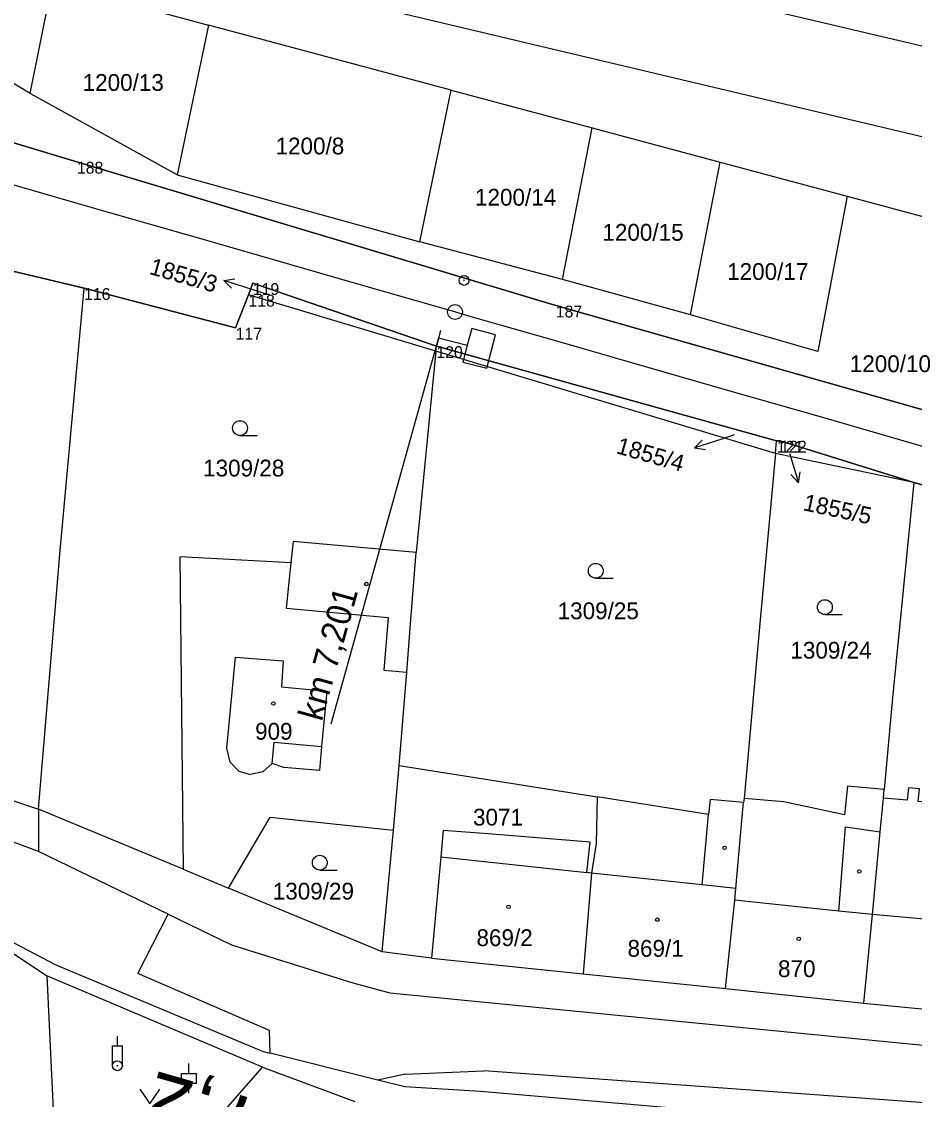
# Model space of a CAD drawing. Extents: x -779330 to -774454, y -1144748 to -1142831.
# Drawn here: x -777328.3 to -777238, y -1143849.7 to -1143740.6 of the extents above; entities that cross this region are included whole.
import ezdxf

# ---------------------------------------------------------------- set-up
doc = ezdxf.new("R2010")
doc.units = 0
for name, color, linetype in [('Hranice parcel', 7, 'Continuous'), ('Parcelní čísla', 7, 'Continuous'), ('Pop  PČ popisy', 7, 'Continuous'), ('Poz předměty', 7, 'Continuous'), ('SŽDC', 7, 'Continuous'), ('Vnitřní kresba', 7, 'Continuous'), ('Vrstva 1', 7, 'Continuous'), ('Vrstva 53', 7, 'Continuous'), ('Vrstva 60', 7, 'Continuous'), ('Vrstva 7', 7, 'Continuous'), ('Značky budov', 7, 'Continuous'), ('Značky kultur', 7, 'Continuous')]:
    doc.layers.add(name, color=color, linetype=linetype)

msp = doc.modelspace()

# ---------------------------------------------------------------- linework, layer by layer
at = {"layer": 'Hranice parcel'}
for p, q in [((-777327.45, -1143747.9), (-777325.2, -1143736.7)), ((-777327.45, -1143747.9), (-777342.31, -1143738.85)), ((-777309.4, -1143740.97), (-777312.56, -1143756.11)), ((-777284.85, -1143747.54), (-777309.4, -1143740.97)), ((-777288.01, -1143762.89), (-777284.85, -1143747.54)), ((-777284.85, -1143747.54), (-777270.58, -1143751.37)), ((-777312.56, -1143756.11), (-777327.45, -1143747.9)), ((-777273.56, -1143766.7), (-777270.58, -1143751.37)), ((-777270.58, -1143751.37), (-777257.62, -1143754.85)), ((-777260.64, -1143770.3), (-777257.62, -1143754.85)), ((-777257.62, -1143754.85), (-777244.78, -1143758.29)), ((-777312.56, -1143756.11), (-777288.01, -1143762.89)), ((-777244.78, -1143758.29), (-777232.23, -1143761.66)), ((-777273.56, -1143766.7), (-777288.01, -1143762.89)), ((-777260.64, -1143770.3), (-777273.56, -1143766.7)), ((-777286.39, -1143773.98), (-777305.36, -1143768.26)), ((-777286.39, -1143773.98), (-777286.34, -1143773.47)), ((-777251.91, -1143783.05), (-777286.34, -1143773.47)), ((-777286.39, -1143773.98), (-777288.38, -1143794.34)), ((-777252.03, -1143784.34), (-777286.39, -1143773.98)), ((-777252.03, -1143784.34), (-777251.91, -1143783.05)), ((-777238.03, -1143787.25), (-777252.03, -1143784.34)), ((-777223.03, -1143791.52), (-777238.03, -1143787.25)), ((-777290.68, -1143822.46), (-777290.09, -1143815.91)), ((-777290.09, -1143815.91), (-777270.07, -1143819.08)), ((-777241.11, -1143819.21), (-777241.04, -1143818.34)), ((-777255.21, -1143819.24), (-777255.25, -1143819.66)), ((-777251.18, -1143819.6), (-777255.21, -1143819.24)), ((-777311.97, -1143826.4), (-777326.6, -1143820.32)), ((-777326.6, -1143820.32), (-777326.59, -1143824.61)), ((-777326.59, -1143824.61), (-777334.23, -1143821.79)), ((-777291.81, -1143834.78), (-777290.68, -1143822.46)), ((-777281.11, -1143822.84), (-777285.64, -1143822.5)), ((-777313.47, -1143830.96), (-777326.59, -1143824.61)), ((-777311.97, -1143826.4), (-777307.37, -1143828.31)), ((-777270.65, -1143826.8), (-777271.48, -1143836.99)), ((-777291.81, -1143834.78), (-777307.37, -1143828.31)), ((-777336.84, -1143829.8), (-777325.74, -1143837.19)), ((-777316.56, -1143836.95), (-777313.47, -1143830.96)), ((-777286.82, -1143835.42), (-777291.81, -1143834.78)), ((-777286.82, -1143835.42), (-777271.48, -1143836.99)), ((-777303.21, -1143842.75), (-777316.56, -1143836.95)), ((-777271.48, -1143836.99), (-777257.08, -1143838.49)), ((-777303.94, -1143846.43), (-777325.74, -1143837.19)), ((-777325.74, -1143837.19), (-777324.77, -1143858.48)), ((-777257.08, -1143838.49), (-777243.1, -1143839.97)), ((-777243.1, -1143839.97), (-777230.13, -1143841.26)), ((-777303.16, -1143845.03), (-777303.21, -1143842.75)), ((-777303.94, -1143846.43), (-777294.6, -1143849.93))]:
    msp.add_line(p, q, dxfattribs=at)
for points in [[(-777325.2, -1143736.7), (-777318.15, -1143738.6), (-777309.4, -1143740.97)], [(-776969.85, -1143863.66), (-776987.47, -1143857.88), (-777014.89, -1143846.57), (-777042.6, -1143836.95), (-777069.03, -1143828.43), (-777082.24, -1143824.08), (-777130.76, -1143810.13), (-777274.26, -1143769.36), (-777322.71, -1143754.8), (-777354.97, -1143745.11)], [(-777244.78, -1143758.29), (-777247.73, -1143773.99), (-777260.64, -1143770.3)], [(-777321.99, -1143767.59), (-777335.02, -1143764.48), (-777339.43, -1143766.44), (-777340.59, -1143770.61), (-777348.72, -1143768.82), (-777354.56, -1143760.13)], [(-777354.56, -1143760.13), (-777350.41, -1143771.21), (-777345.05, -1143784.18), (-777331.15, -1143818.8), (-777326.6, -1143820.32)], [(-777286.34, -1143773.47), (-777304.91, -1143767.08), (-777305.36, -1143768.26)], [(-777326.6, -1143820.32), (-777324.39, -1143794.13), (-777321.99, -1143767.59)], [(-777305.36, -1143768.26), (-777306.65, -1143771.6), (-777321.99, -1143767.59)], [(-777238.03, -1143787.25), (-777251.55, -1143783.03), (-777251.91, -1143783.05)], [(-777252.03, -1143784.34), (-777253.62, -1143801.54), (-777255.21, -1143819.24)], [(-777238.03, -1143787.25), (-777240.18, -1143809.05), (-777241.04, -1143818.34)], [(-777288.38, -1143794.34), (-777300.82, -1143793.24), (-777301.05, -1143795.41), (-777312.29, -1143794.79), (-777311.97, -1143826.4)], [(-777290.09, -1143815.91), (-777289.33, -1143806.45), (-777288.91, -1143801.12), (-777288.38, -1143794.34)], [(-777241.04, -1143818.34), (-777244.73, -1143818), (-777245.06, -1143820.91), (-777251.18, -1143819.6)], [(-777227.11, -1143820.99), (-777234.21, -1143819.88), (-777237.58, -1143819.54), (-777237.46, -1143818.26), (-777238.58, -1143818.16), (-777238.7, -1143819.43), (-777241.11, -1143819.21)], [(-777270.07, -1143819.08), (-777270.18, -1143823.82), (-777270.65, -1143826.8)], [(-777255.25, -1143819.66), (-777258.65, -1143819.35), (-777258.79, -1143820.87), (-777270.07, -1143819.08)], [(-777256.03, -1143828.35), (-777255.35, -1143820.74), (-777255.25, -1143819.66)], [(-777243.1, -1143839.97), (-777242.2, -1143831), (-777241.43, -1143822.63), (-777241.11, -1143819.21)], [(-777307.37, -1143828.31), (-777303.15, -1143821.13), (-777290.68, -1143822.46)], [(-777285.64, -1143822.5), (-777285.88, -1143825.17), (-777286.82, -1143835.42)], [(-777270.65, -1143826.8), (-777271.1, -1143826.75), (-777270.77, -1143823.67), (-777281.11, -1143822.84)], [(-777257.08, -1143838.49), (-777256.14, -1143829.55), (-777256.03, -1143828.35)], [(-777336.84, -1143829.8), (-777324.83, -1143836.1), (-777303.85, -1143844.86), (-777303.16, -1143845.03)], [(-777313.47, -1143830.96), (-777307.07, -1143834.06), (-777294.79, -1143837.91), (-777291.06, -1143838.91), (-777215.44, -1143846.33), (-777156.34, -1143852.08), (-777155.61, -1143848.73), (-777137.5, -1143850.27)], [(-776998.39, -1143882.22), (-777014.02, -1143874.66), (-777035.36, -1143870.54), (-777167.58, -1143858.82), (-777281.88, -1143848.9), (-777289.53, -1143848.43), (-777292.27, -1143847.75), (-777303.16, -1143845.03)], [(-777322.91, -1143859.24), (-777317.16, -1143861.59), (-777303.94, -1143846.43)]]:
    msp.add_lwpolyline(points, dxfattribs=at)
at = {"layer": 'Pop  PČ popisy'}
for p, q in [((-777307.84, -1143766.8), (-777306.74, -1143766.64)), ((-777304.99, -1143767.73), (-777307.84, -1143766.8)), ((-777307.84, -1143766.8), (-777307.05, -1143767.59)), ((-777303.43, -1143768.24), (-777304.99, -1143767.73)), ((-777256.2, -1143782.45), (-777257.37, -1143782.84)), ((-777257.37, -1143782.84), (-777260.22, -1143783.77)), ((-777260.22, -1143783.77), (-777259.43, -1143782.98)), ((-777260.22, -1143783.77), (-777259.12, -1143783.93)), ((-777250.61, -1143784.33), (-777250.59, -1143784.41)), ((-777250.59, -1143784.41), (-777249.71, -1143787.28)), ((-777249.71, -1143787.28), (-777250.48, -1143786.47)), ((-777249.71, -1143787.28), (-777249.53, -1143786.18))]:
    msp.add_line(p, q, dxfattribs=at)
at = {"layer": 'Poz předměty'}
for p, q in [((-777318.61, -1143844.3), (-777318.61, -1143843.3)), ((-777319.11, -1143844.3), (-777318.11, -1143844.3)), ((-777319.11, -1143846.3), (-777319.11, -1143844.3)), ((-777318.11, -1143846.3), (-777318.11, -1143844.3))]:
    msp.add_line(p, q, dxfattribs=at)
for radius in [0.5, 0.0303]:
    msp.add_circle((-777318.61, -1143846.3), radius, dxfattribs=at)
at = {"layer": 'SŽDC'}
for points in [[(-777130.76, -1143810.13), (-777274.26, -1143769.36), (-777322.71, -1143754.8), (-777354.97, -1143745.11), (-777360.64, -1143743.54), (-777364.22, -1143742.54), (-777366.62, -1143741.88), (-777370.73, -1143741.3), (-777400.53, -1143733.41), (-777442.54, -1143720.48), (-777447.49, -1143719.07), (-777546.18, -1143690.99), (-777600.4, -1143675.56), (-777619.92, -1143670.03)], [(-777340.59, -1143770.61), (-777339.43, -1143766.44), (-777335.02, -1143764.48), (-777321.99, -1143767.59), (-777306.65, -1143771.6), (-777305.36, -1143768.26), (-777304.91, -1143767.08), (-777286.34, -1143773.47), (-777251.91, -1143783.05), (-777251.55, -1143783.03), (-777238.03, -1143787.25), (-777223.03, -1143791.52), (-777208.67, -1143795.71), (-777200.02, -1143798.42), (-777184.53, -1143802.76), (-777180.06, -1143803.98), (-777171.85, -1143806.53), (-777132.17, -1143818.13)]]:
    msp.add_lwpolyline(points, dxfattribs=at)
at = {"layer": 'Vnitřní kresba'}
for p, q in [((-777312.68, -1143725.18), (-777111.56, -1143772.88)), ((-777113.15, -1143781.74), (-777316.11, -1143733.54)), ((-777301.05, -1143795.41), (-777301.54, -1143800)), ((-777301.54, -1143800), (-777291.2, -1143800.92)), ((-777291.2, -1143800.92), (-777291.66, -1143806.27)), ((-777307.53, -1143814.17), (-777306.67, -1143804.95)), ((-777306.67, -1143804.95), (-777301.84, -1143805.3)), ((-777301.84, -1143805.3), (-777302.02, -1143807.96)), ((-777291.66, -1143806.27), (-777289.33, -1143806.45)), ((-777302.02, -1143807.96), (-777297.43, -1143808.38)), ((-777297.43, -1143808.38), (-777297.95, -1143813.99)), ((-777307.2, -1143815.56), (-777307.53, -1143814.17)), ((-777302.94, -1143815.72), (-777302.75, -1143813.55)), ((-777302.75, -1143813.55), (-777297.95, -1143813.99)), ((-777297.95, -1143813.99), (-777298.17, -1143816.4)), ((-777306.31, -1143816.47), (-777307.2, -1143815.56)), ((-777303.9, -1143816.56), (-777302.94, -1143815.72)), ((-777301.78, -1143816.1), (-777302.94, -1143815.72)), ((-777298.17, -1143816.4), (-777301.78, -1143816.1)), ((-777306.31, -1143816.47), (-777305.15, -1143816.82)), ((-777303.9, -1143816.56), (-777305.15, -1143816.82)), ((-777259.43, -1143827.99), (-777258.79, -1143820.87)), ((-777245.61, -1143830.64), (-777244.96, -1143822.12)), ((-777244.96, -1143822.12), (-777241.43, -1143822.63)), ((-777285.88, -1143825.17), (-777271.1, -1143826.75)), ((-777259.43, -1143827.99), (-777270.65, -1143826.8)), ((-777256.03, -1143828.35), (-777259.43, -1143827.99)), ((-777253.62, -1143829.81), (-777256.14, -1143829.55)), ((-777245.61, -1143830.64), (-777253.62, -1143829.81)), ((-777242.2, -1143831), (-777245.61, -1143830.64)), ((-777230.17, -1143832.07), (-777242.2, -1143831)), ((-777289.51, -1143847.16), (-777281.53, -1143846.8)), ((-777216.02, -1143851.57), (-777281.53, -1143846.8)), ((-777289.51, -1143847.16), (-777292.27, -1143847.75))]:
    msp.add_line(p, q, dxfattribs=at)
at = {"layer": 'Vrstva 1'}
msp.add_lwpolyline([(-777162.91, -1143804.93), (-777170.68, -1143802.7), (-777181.57, -1143799.57), (-777188.57, -1143797.56), (-777198.81, -1143794.61), (-777207.68, -1143792.07), (-777219.79, -1143788.59), (-777229.54, -1143785.79), (-777237.24, -1143783.57), (-777247.71, -1143780.56), (-777256.74, -1143777.97), (-777268.3, -1143774.64), (-777273.69, -1143773.09), (-777283.04, -1143770.41), (-777284.04, -1143770.12), (-777284.38, -1143770.02), (-777293.19, -1143767.49), (-777295.09, -1143766.94), (-777310.28, -1143762.58), (-777319.98, -1143759.79), (-777330, -1143756.91)], dxfattribs=at)
at = {"layer": 'Vrstva 53'}
for points in [[(-777619.92, -1143670.03), (-777600.4, -1143675.56), (-777546.18, -1143690.99), (-777447.49, -1143719.07), (-777442.54, -1143720.48), (-777400.53, -1143733.41), (-777370.73, -1143741.3), (-777366.62, -1143741.88), (-777364.22, -1143742.54), (-777360.64, -1143743.54), (-777354.97, -1143745.11), (-777322.71, -1143754.8), (-777274.26, -1143769.36), (-777130.76, -1143810.13)], [(-777619.92, -1143670.03), (-777600.4, -1143675.56), (-777546.18, -1143690.99), (-777447.49, -1143719.07), (-777442.54, -1143720.48), (-777400.53, -1143733.41), (-777370.73, -1143741.3), (-777366.62, -1143741.88), (-777364.22, -1143742.54), (-777360.64, -1143743.54), (-777354.97, -1143745.11), (-777322.71, -1143754.8), (-777274.26, -1143769.36), (-777130.76, -1143810.13)], [(-777132.17, -1143818.13), (-777171.85, -1143806.53), (-777180.06, -1143803.98), (-777184.53, -1143802.76), (-777200.02, -1143798.42), (-777208.67, -1143795.71), (-777223.03, -1143791.52), (-777238.03, -1143787.25), (-777251.55, -1143783.03), (-777251.91, -1143783.05), (-777286.34, -1143773.47), (-777304.91, -1143767.08), (-777305.36, -1143768.26), (-777306.65, -1143771.6), (-777321.99, -1143767.59), (-777335.02, -1143764.48), (-777339.43, -1143766.44), (-777340.59, -1143770.61)], [(-777132.17, -1143818.13), (-777171.85, -1143806.53), (-777180.06, -1143803.98), (-777184.53, -1143802.76), (-777200.02, -1143798.42), (-777208.67, -1143795.71), (-777223.03, -1143791.52), (-777238.03, -1143787.25), (-777251.55, -1143783.03), (-777251.91, -1143783.05), (-777286.34, -1143773.47), (-777304.91, -1143767.08), (-777305.36, -1143768.26), (-777306.65, -1143771.6), (-777321.99, -1143767.59), (-777335.02, -1143764.48), (-777339.43, -1143766.44), (-777340.59, -1143770.61)]]:
    msp.add_lwpolyline(points, dxfattribs=at)
at = {"layer": 'Vrstva 60'}
for p, q in [((-777322.71, -1143754.8), (-777322.71, -1143754.8)), ((-777304.91, -1143767.08), (-777304.91, -1143767.08)), ((-777321.99, -1143767.59), (-777321.99, -1143767.59)), ((-777305.36, -1143768.26), (-777305.36, -1143768.26)), ((-777274.26, -1143769.36), (-777274.26, -1143769.36)), ((-777306.65, -1143771.6), (-777306.65, -1143771.6)), ((-777286.34, -1143773.47), (-777286.34, -1143773.47)), ((-777251.91, -1143783.05), (-777251.91, -1143783.05)), ((-777251.55, -1143783.03), (-777251.55, -1143783.03)), ((-777238.03, -1143787.25), (-777238.03, -1143787.25))]:
    msp.add_line(p, q, dxfattribs=at)
at = {"layer": 'Vrstva 7'}
for p, q in [((-777283.49, -1143766.82), (-777283.59, -1143766.8)), ((-777286.11, -1143772.61), (-777297.03, -1143811.73)), ((-777285.92, -1143771.89), (-777286.3, -1143773.34))]:
    msp.add_line(p, q, dxfattribs=at)
msp.add_lwpolyline([(-777286.11, -1143772.61), (-777283.21, -1143773.37), (-777283.65, -1143775.07), (-777281.24, -1143775.7), (-777280.35, -1143772.32), (-777282.76, -1143771.68), (-777283.21, -1143773.37)], dxfattribs=at)
for centre, radius in [((-777283.54, -1143766.81), 0.5), ((-777284.45, -1143770), 0.75)]:
    msp.add_circle(centre, radius, dxfattribs=at)
at = {"layer": 'Značky budov'}
for centre in [(-777293.43, -1143797.54), (-777302.83, -1143809.63), (-777257.18, -1143824.24), (-777243.55, -1143826.64), (-777279.04, -1143830.22), (-777263.98, -1143831.52), (-777249.68, -1143833.46)]:
    msp.add_circle(centre, 0.175, dxfattribs=at)
at = {"layer": 'Značky kultur'}
for p, q in [((-777306.21, -1143782.51), (-777304.46, -1143782.51)), ((-777270.21, -1143796.95), (-777268.46, -1143796.95)), ((-777247.03, -1143800.63), (-777245.28, -1143800.63)), ((-777298.13, -1143826.49), (-777296.38, -1143826.49)), ((-777311.37, -1143847.07), (-777311.37, -1143846.07)), ((-777312.12, -1143847.07), (-777310.62, -1143847.07)), ((-777312.12, -1143848.07), (-777312.12, -1143847.07)), ((-777310.62, -1143848.07), (-777310.62, -1143847.07)), ((-777312.12, -1143848.07), (-777310.62, -1143848.07)), ((-777311.37, -1143849.07), (-777311.37, -1143848.07))]:
    msp.add_line(p, q, dxfattribs=at)
msp.add_lwpolyline([(-777316.33, -1143848.67), (-777315.33, -1143850.17), (-777314.33, -1143848.67)], dxfattribs=at)
for centre in [(-777306.21, -1143781.76), (-777270.21, -1143796.2), (-777247.03, -1143799.88), (-777298.13, -1143825.74)]:
    msp.add_circle(centre, 0.75, dxfattribs=at)

# ---------------------------------------------------------------- texts
at = {"layer": 'Parcelní čísla'}
for s, p in [('1200/13', (-777322.13, -1143747.62)), ('1200/8', (-777302.61, -1143754.05)), ('1200/14', (-777282.43, -1143759.24)), ('1200/15', (-777269.54, -1143762.79)), ('1200/17', (-777256.92, -1143766.76)), ('1200/10', (-777244.51, -1143776.09)), ('1309/28', (-777309.94, -1143786.65)), ('1309/25', (-777274.07, -1143801.1)), ('1309/24', (-777250.52, -1143805.09)), ('909', (-777304.68, -1143813.3)), ('3071', (-777282.63, -1143821.99)), ('1309/29', (-777302.89, -1143829.48)), ('869/2', (-777282.28, -1143834.19)), ('869/1', (-777267, -1143835.27)), ('870', (-777251.77, -1143837.33))]:
    msp.add_text(s, height=1.7, dxfattribs=at).set_placement(p)
for s, rotation, p in [('1855/3', 344, (-777315.48, -1143766.14)), ('1855/4', 344, (-777268.24, -1143784.28)), ('1855/5', 348, (-777249.31, -1143790.06))]:
    msp.add_text(s, height=1.7, rotation=rotation, dxfattribs=at).set_placement(p)
at = {"layer": 'Vrstva 60'}
for s, p in [('188', (-777322.71, -1143756)), ('119', (-777304.91, -1143768.28)), ('116', (-777321.99, -1143768.79)), ('118', (-777305.36, -1143769.46)), ('187', (-777274.26, -1143770.56)), ('117', (-777306.65, -1143772.8)), ('120', (-777286.34, -1143774.67)), ('121', (-777251.91, -1143784.25)), ('122', (-777251.55, -1143784.23))]:
    msp.add_text(s, height=1.2, dxfattribs=at).set_placement(p)
at = {"layer": 'Vrstva 7'}
for s, height, rotation, p in [('km 7,201', 2.5, 74.3963, (-777297.94, -1143811.53)), ('7,2', 6, 163.9643, (-777304.1, -1143849.86))]:
    msp.add_text(s, height=height, rotation=rotation, dxfattribs=at).set_placement(p)

doc.saveas('drawing.dxf')
